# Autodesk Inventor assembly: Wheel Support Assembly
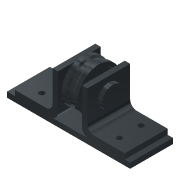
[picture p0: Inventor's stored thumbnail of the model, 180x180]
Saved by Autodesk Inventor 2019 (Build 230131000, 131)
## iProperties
Created: 2016-08
Part Number: Wheel Support Assembly
Document SubType Name: Assembly
Designer: Sandeep
Author: Sandeep
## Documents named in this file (5)
- E:\_Deepak\Inventor\Projects\Autodesk Inventor_2019_Project\Resources\Inventor_2018_tut\c15_Inv_2019_tut\c15_Inv_tut_2019\c15_tut03_inv\Wheel Support Assembly.iam
- E:\_Deepak\Inventor\Projects\Autodesk Inventor_2019_Project\Resources\Inventor_2018_tut\c15_Inv_2019_tut\c15_Inv_tut_2019\c15_tut03_inv\base.ipt
- E:\_Deepak\Inventor\Projects\Autodesk Inventor_2019_Project\Resources\Inventor_2018_tut\c15_Inv_2019_tut\c15_Inv_tut_2019\c15_tut03_inv\Support.ipt
- E:\_Deepak\Inventor\Projects\Autodesk Inventor_2019_Project\Resources\Inventor_2018_tut\c15_Inv_2019_tut\c15_Inv_tut_2019\c15_tut03_inv\Wheel.ipt
- E:\_Deepak\Inventor\Projects\Autodesk Inventor_2019_Project\Resources\Inventor_2018_tut\c15_Inv_2019_tut\c15_Inv_tut_2019\c15_tut03_inv\Shoulder screw.ipt
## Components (5 placed, 4 different names)
1. base:1 — Insert:1, Mate:1, Insert:2, Mate:2
2. Support:1 — Insert:1, Mate:1, Insert:3
3. Support:2 — Insert:2, Mate:2, Mate:3, Mate:4
4. Wheel:1 — Insert:3
5. Shoulder screw:1 — Mate:3, Mate:4
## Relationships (7: Mate 4, Insert 3)
- Insert:1: base:1 ↔ Support:1
- Mate:1: base:1 ↔ Support:1
- Insert:2: base:1 ↔ Support:2
- Mate:2: base:1 ↔ Support:2
- Insert:3: Support:1 ↔ Wheel:1
- Mate:3: Support:2 ↔ Shoulder screw:1
- Mate:4: Support:2 ↔ Shoulder screw:1
